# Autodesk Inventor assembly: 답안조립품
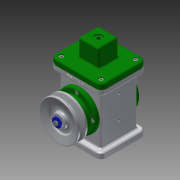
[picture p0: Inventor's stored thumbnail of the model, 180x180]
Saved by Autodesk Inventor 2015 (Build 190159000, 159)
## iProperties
Created: 2017-08
Part Number: 답안조립품
Document SubType Name: Assembly
Designer: Administrator
Author: Administrator
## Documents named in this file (17)
- C:\Users\Administrator\Desktop\470807V1003\답안조립품.iam
- C:\Users\Administrator\Desktop\470807V1003\본체.ipt
- C:\Users\Administrator\Desktop\470807V1003\부품\E-링.ipt
- C:\Users\Administrator\Desktop\470807V1003\부품\V-벨트풀리.ipt
- C:\Users\Administrator\Desktop\470807V1003\부품\덮개.ipt
- C:\Users\Administrator\Desktop\470807V1003\부품\뒤커버.ipt
- C:\Users\Administrator\Desktop\470807V1003\부품\링크.ipt
- C:\Users\Administrator\Desktop\470807V1003\부품\베어링 17 x 40 x 12.ipt
- C:\Users\Administrator\Desktop\470807V1003\부품\볼트 M4 x 8.ipt
- C:\Users\Administrator\Desktop\470807V1003\부품\볼트 M4 x 10.ipt
- C:\Users\Administrator\Desktop\470807V1003\부품\슬라이더.ipt
- C:\Users\Administrator\Desktop\470807V1003\부품\앞커버.ipt
- C:\Users\Administrator\Desktop\470807V1003\부품\오일 실 17 30 8.ipt
- C:\Users\Administrator\Desktop\470807V1003\부품\와셔 4x16.ipt
- C:\Users\Administrator\Desktop\470807V1003\부품\클레비스 핀 6 x 22.ipt
- C:\Users\Administrator\Desktop\470807V1003\부품\키 4 x 4 x 12.ipt
- C:\Users\Administrator\Desktop\470807V1003\부품\편심축.ipt
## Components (2 placed, 2 different names)
1. E-링:1
2. V-벨트풀리:1
